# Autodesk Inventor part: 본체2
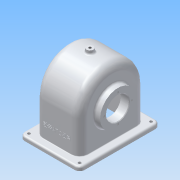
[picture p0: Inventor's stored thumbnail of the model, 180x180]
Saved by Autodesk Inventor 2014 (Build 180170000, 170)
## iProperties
Created: 2016-01
Part Number: 본체2
Material: 알루미늄 6061
Document SubType Name: Modeling
Designer: User
Mass: 794.903 g
Surface Area: 1006.9 cm^2
Volume: 293.322 cm^3
Density: 2.71 g/cm^3
Appearance: 알루미늄 - 평지
Author: User
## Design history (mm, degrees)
sketch "스케치1"
  geometry: L1 (-57, 0)-(57, 0); L2 (57, 0)-(57, -64); L3 (57, -64)-(-57, -64); L4 (-57, -64)-(-57, 0); C1 r 57 at (0, 0); 2 further points
  constraints: 8 end point, 2 coincident, 2 parallel, 1 centre point, 1 horizontal, 1 midpoint, 1 perpendicular
  dimensions: "d0" = 114 diameter of C1; "d1" = 114 distance of L2.end L3.end; "d2" = 64 distance of L1.end L2.end
extrude "돌출1" new body sketch "스케치1" stored distance "d3" = 77; taper "d4" = 0 deg
feature "쉘1" dims "d7" = 6
sketch "스케치3"
  geometry: L1 (114, 0)-(114, -77) reference; L2 (0, 0)-(114, 0) reference; L3 (0, 0)-(0, -77) reference; L4 (114, -77)-(0, -77) reference; L5 (-13, 13.5)-(127, 13.5); L6 (127, 13.5)-(127, -90.5); L7 (127, -90.5)-(-13, -90.5); L8 (-13, -90.5)-(-13, 13.5); 3 further points
  constraints: 8 end point, 2 midpoint, 2 parallel, 1 horizontal, 1 horizontal alignment, 1 perpendicular, 1 vertical alignment
  dimensions: "d8" = 140 distance of L5.start L5.end; "d9" = 104 distance of L5.end L6.end
extrude "돌출2" join sketch "스케치3" distance "d10" = 7; taper "d11" = 0 deg
fillet "모깎기1" dims "d12" = 14
node "작업 평면1"
sketch "스케치6"
  geometry: C1 r 6 at (0, 0); 1 further point
  constraints: 1 centre point, 1 coincident
  dimensions: "d36" = 12 diameter of C1
extrude "돌출4" join sketch "스케치6" stored distance "d37" = 10; taper "d38" = 0 deg
hole "구멍2" diameter "d41" = 4.459; stored, may be unused: countersink angle "d45" = 90 deg, drill point angle "d47" = 118 deg; dims "d39" = 10, "d40" = 10, "d42" = 6, "d43" = 4, "d44" = 2, "d46" = 63
fillet "모깎기4" dims "d77" = 8
sketch "스케치9"
  geometry: A1 r 8 centre (119, 82.5) between (127, 82.5) and (119, 90.5) reference; A2 r 8 centre (-5, 82.5) between (-5, 90.5) and (-13, 82.5) reference; A3 r 8 centre (-5, -5.5) between (-13, -5.5) and (-5, -13.5) reference; A4 r 8 centre (119, -5.5) between (119, -13.5) and (127, -5.5) reference; 1 further point
hole "구멍5" sketch "스케치9" at (119, 82.5), (-5, 82.5), (119, -5.5), (-5, -5.5) diameter "d78" = 5; stored, may be unused: countersink angle "d82" = 90 deg, drill point angle "d84" = 118 deg; dims "d79" = 7, "d80" = 4, "d81" = 2, "d83" = 9
fillet "모깎기5" dims "d85" = 3
sketch "스케치10"
  geometry: L1 (49, 0)-(49, -57) reference; L2 (0, 0)-(49, 0) reference; L3 (0, -57)-(0, 0) reference; L4 (-1.387, -30.398)-(50.387, -30.398); L5 (50.387, -30.398)-(50.387, -37.602); L6 (50.387, -37.602)-(-1.387, -37.602); L7 (-1.387, -37.602)-(-1.387, -30.398); L8 (0, -34)-(49, -34); L9 (-19.5, -64)-(68.5, -64) reference; L10 (24.5, 0)-(24.5, -54); L11 (-14, 0)-(-14, -57) reference; L12 (68.5, -57)-(-19.5, -57) reference; 4 further points
  constraints: 4 end point, 4 midpoint, 2 point on line, 1 horizontal alignment, 1 perpendicular, 1 vertical alignment, 2 other
  dimensions: "d86" = 30 distance between parallel lines of L9 L8; "d87" = 38.5 distance between parallel lines of L11 L10
feature "엠보싱1" sketch "스케치10" dims "d8" = 140, "d9" = 104, "d88" = 0.5, "d89" = 0
sketch "스케치11"
  geometry: L1 (-51, -64)-(-51, 0) reference; L2 (51, -64)-(-51, -64) reference; L3 (51, 0)-(51, -64) reference; C1 r 20 at (0, -4) reference; A1 r 51 centre (0, 0) between (51, 0) and (-51, 0) reference
extrude "돌출5" cut sketch "스케치11" distance "d90" = 1; taper "d91" = 0 deg
sketch "스케치12"
  geometry: L1 (-51, -64)-(-51, 0) reference; L2 (51, -64)-(-51, -64) reference; L3 (51, 0)-(51, -64) reference; C1 r 38.908 at (0, -4) reference; A1 r 51 centre (0, 0) between (51, 0) and (-51, 0) reference
extrude "돌출6" cut sketch "스케치12" distance "d92" = 1; taper "d93" = 0 deg
sketch "스케치13"
  geometry: L1 (-4, 43.197)-(-4, -48.942); L2 (-64, -33.5)-(-64, 33.5) reference; L3 (16, 35.5)-(30.899, 35.5); L4 (24, 35.5)-(24, 19.5); L5 (24, 19.5)-(16, 19.5); L6 (16, 19.5)-(16, 35.5); L7 (0, 38.5)-(43, 38.5) reference; L8 (24, 19.5)-(39.943, 38.5); L9 (30.899, 35.5)-(33.416, 38.5); L10 (-4, 33.5)-(16, 33.5); L11 (-4, 38.5)-(33.416, 38.5); L12 (-4, 38.5)-(-4, 33.5); 1 further point
  constraints: 20 end point, 6 point on line, 3 parallel, 2 perpendicular, 1 collinear, 1 horizontal, 1 vertical
  dimensions: "d95" = 60 distance between parallel lines of L1 L2; "d96" = 20 distance between parallel lines of L1 L6; "d99" = 50 deg angle of L8 L5; "d100" = 5 distance between parallel lines of L8 L9; "d102" = 5 distance between parallel lines of L10 L11; "d103" = 56 diameter of L4 L1; "d104" = 19 distance between parallel lines of L11 L5; "d105" = 3 distance between parallel lines of L11 L3
revolve "회전3" stored, may be unused: angle "d106" = 90 deg
revolve "회전4" stored, may be unused: angle "d107" = 90 deg
sketch "스케치14"
  geometry: C1 r 20 at (0, -4) reference; C2 r 31 at (0, -4)
  constraints: 1 centre point, 1 coincident
  dimensions: "d108" = 62 diameter of C2
extrude "돌출7" join sketch "스케치14" distance "d109" = 10; taper "d110" = 0 deg
hole "구멍6" diameter "d113" = 40; stored, may be unused: countersink angle "d117" = 90 deg, drill point angle "d119" = 118 deg; dims "d111" = 10, "d112" = 10, "d114" = 6, "d115" = 4, "d116" = 2, "d118" = 8
chamfer "모따기3" distance "d120" = 1; stored, may be unused: second distance "d121" = 2, angle "d122" = 45 deg
fillet "모깎기6" dims "d123" = 3
sketch "스케치15"
  geometry: C1 r 31 at (0, 0) reference; 2 further points
  constraints: 1 vertical alignment
  dimensions: "d124" = 24 distance of C1.centre point (0, 24)
hole "구멍7" sketch "스케치15" at (0, 24) diameter "d125" = 2.459; stored, may be unused: countersink angle "d129" = 90 deg, drill point angle "d131" = 118 deg; dims "d126" = 6, "d127" = 4, "d128" = 2, "d130" = 8
sketch "스케치16"
  geometry: C1 r 21 at (0, 0) reference; 2 further points
  constraints: 1 vertical alignment
  dimensions: "d135" = 28 distance of C1.centre point (0, 28)
hole "구멍8" sketch "스케치16" at (0, 28) diameter "d136" = 2.459; stored, may be unused: countersink angle "d140" = 90 deg, drill point angle "d142" = 118 deg; dims "d137" = 7, "d138" = 4, "d139" = 2, "d141" = 9
fillet "모깎기7" dims "d146" = 6
fillet "모깎기8" dims "d147" = 3
fillet "모깎기9" dims "d148" = 1
node "솔리드1"
pattern_circular "원형 패턴3" dims angle "d133" = 360 deg
pattern_circular "원형 패턴4" dims angle "d144" = 360 deg
other parameters: "d35" = 63
